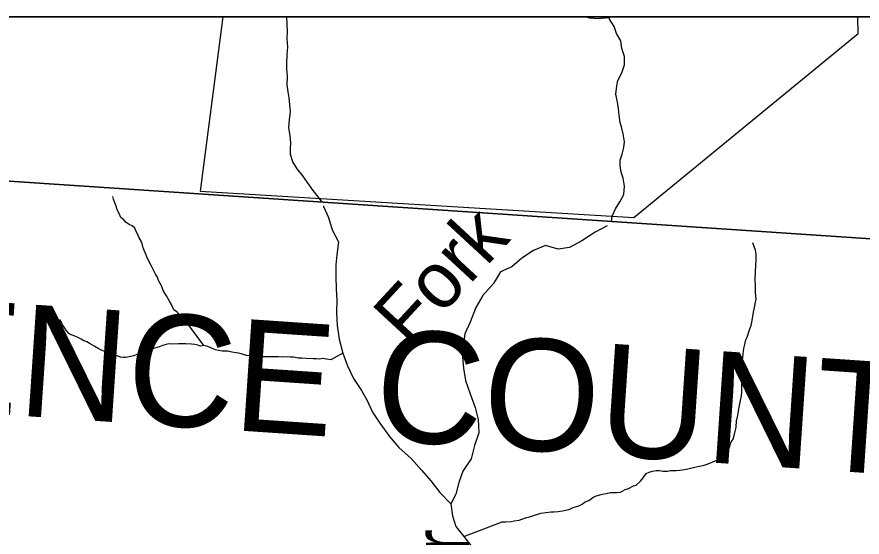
# Model space of a CAD drawing. Extents: x 0 to 34, y 0 to 22.
# Drawn here: x 4.61 to 6.043, y 20.019 to 20.9 of the extents above; entities that cross this region are included whole.
import ezdxf

# ---------------------------------------------------------------- set-up
doc = ezdxf.new("R2010")
doc.units = 0
for name, color, linetype in [('GM_X_County_Text', 7, 'Continuous'), ('GM_X_Minor_River', 7, 'Continuous'), ('GM_X_Minor_River_Text', 7, 'Continuous'), ('GM_X_Township_Road_Text', 7, 'Continuous'), ('GM_X_Unincorporated', 7, 'Continuous'), ('SH_Cut_Line', 7, 'Continuous'), ('SH_Data', 7, 'Continuous')]:
    doc.layers.add(name, color=color, linetype=linetype)

msp = doc.modelspace()

# ---------------------------------------------------------------- linework, layer by layer
at = {"layer": 'GM_X_Minor_River'}
for points in [[(5.1277, 20.5859), (5.1227, 20.5926), (5.1125, 20.6059), (5.1027, 20.6192), (5.0945, 20.6306), (5.085, 20.6424), (5.0775, 20.6542), (5.0737, 20.6671), (5.0738, 20.677), (5.0746, 20.6865), (5.0731, 20.699), (5.0709, 20.7119), (5.0721, 20.7263), (5.0736, 20.7392), (5.0729, 20.751), (5.0714, 20.7631), (5.0696, 20.773), (5.0681, 20.7851), (5.0685, 20.7988), (5.0678, 20.8117), (5.0675, 20.8215), (5.0683, 20.8359), (5.0691, 20.8492), (5.0684, 20.8629), (5.0688, 20.8754), (5.0684, 20.8875), (5.0677, 20.8997), (5.0676, 20.9)], [(5.6145, 20.8986), (5.6071, 20.898), (5.595, 20.8969), (5.581, 20.8981), (5.5725, 20.9)], [(5.6178, 20.5531), (5.6192, 20.5622), (5.625, 20.5751), (5.6318, 20.5865), (5.6387, 20.599), (5.6399, 20.613), (5.638, 20.627), (5.6343, 20.6369), (5.6324, 20.6475), (5.6328, 20.6574), (5.6359, 20.6673), (5.6386, 20.6786), (5.6397, 20.6881), (5.6375, 20.7021), (5.6353, 20.7116), (5.6327, 20.7211), (5.6308, 20.7337), (5.6297, 20.745), (5.6282, 20.7553), (5.6252, 20.769), (5.6272, 20.783), (5.6284, 20.7925), (5.6356, 20.8053), (5.6402, 20.819), (5.6402, 20.833), (5.6357, 20.8467), (5.6335, 20.8592), (5.6267, 20.8717), (5.6222, 20.8839), (5.6143, 20.8961), (5.6146, 20.9)], [(4.9271, 20.3435), (4.8927, 20.3892), (4.8867, 20.3942), (4.8818, 20.3996), (4.8762, 20.4038), (4.8725, 20.4118), (4.8688, 20.4184), (4.8636, 20.4272), (4.861, 20.4321), (4.858, 20.4367), (4.8558, 20.4432), (4.8528, 20.4486), (4.8502, 20.4532), (4.8484, 20.4593), (4.845, 20.4643), (4.8417, 20.4711), (4.838, 20.4777), (4.8342, 20.4849), (4.8302, 20.4937), (4.8283, 20.4983), (4.8261, 20.5033), (4.8243, 20.5086), (4.8228, 20.5136), (4.8206, 20.5201), (4.8173, 20.5258), (4.8147, 20.5323), (4.8117, 20.5377), (4.8099, 20.5419), (4.8054, 20.5461), (4.8005, 20.5484), (4.7952, 20.5519), (4.7914, 20.5562), (4.7862, 20.5604), (4.7832, 20.5669), (4.7799, 20.5734), (4.7781, 20.5791), (4.7758, 20.5849), (4.7736, 20.5914), (4.7729, 20.5955)], [(5.1295, 20.5797), (5.13, 20.579), (5.1382, 20.5603), (5.1445, 20.539), (5.1554, 20.5192), (5.1526, 20.4972), (5.1509, 20.4798), (5.1504, 20.4604), (5.1514, 20.4391), (5.1524, 20.4201), (5.1519, 20.3992), (5.1529, 20.3772), (5.1565, 20.354), (5.1624, 20.3301), (5.1706, 20.3087), (5.1804, 20.2874), (5.1939, 20.2672), (5.2036, 20.2501), (5.2126, 20.2303), (5.2254, 20.212), (5.2415, 20.1891), (5.2573, 20.1704), (5.2784, 20.1521), (5.2965, 20.1315), (5.3115, 20.1139), (5.327, 20.0941), (5.3454, 20.075), (5.3483, 20.0549), (5.3543, 20.0366), (5.3674, 20.0195), (5.3828, 20)], [(5.6108, 20.5458), (5.5904, 20.5352), (5.5676, 20.5205), (5.5467, 20.5096), (5.5273, 20.5063), (5.5061, 20.5125), (5.4856, 20.5042), (5.4661, 20.4914), (5.449, 20.4767), (5.43, 20.4684), (5.4177, 20.4484), (5.4001, 20.4279), (5.3878, 20.4075), (5.3786, 20.3829), (5.3693, 20.3632), (5.3665, 20.3415), (5.3653, 20.3237), (5.367, 20.3047), (5.3703, 20.2841), (5.3781, 20.2613), (5.3867, 20.2381), (5.3919, 20.218), (5.3929, 20.1955), (5.3859, 20.1739), (5.3801, 20.1516), (5.3659, 20.1307), (5.3589, 20.1114), (5.3542, 20.0913), (5.3454, 20.075)], [(5.8547, 20.3773), (5.8563, 20.3857), (5.8587, 20.3997), (5.8599, 20.405), (5.862, 20.4168), (5.8631, 20.4213), (5.8625, 20.4274), (5.8621, 20.4331), (5.8619, 20.4419), (5.8619, 20.4464), (5.8616, 20.4529), (5.8617, 20.4582), (5.8622, 20.4666), (5.8627, 20.481), (5.8631, 20.4855), (5.8632, 20.4924), (5.8629, 20.4981), (5.8622, 20.5046), (5.8574, 20.5175)], [(5.1624, 20.3301), (5.1419, 20.3191), (5.1351, 20.32), (5.1283, 20.3212), (5.1237, 20.3201), (5.1173, 20.3206), (5.1123, 20.321), (5.0998, 20.3212), (5.0926, 20.322), (5.0869, 20.3221), (5.079, 20.3233), (5.0737, 20.3234), (5.0691, 20.3242), (5.06, 20.3236), (5.0536, 20.324), (5.0467, 20.3241), (5.0392, 20.3242), (5.0335, 20.3239), (5.0263, 20.3244), (5.0209, 20.3248), (5.0122, 20.3253), (5.0069, 20.3261), (4.9993, 20.3266), (4.9903, 20.3294), (4.9857, 20.3302), (4.9816, 20.331), (4.9744, 20.3323), (4.9676, 20.3335), (4.9623, 20.3339), (4.9581, 20.334), (4.952, 20.3348), (4.9467, 20.336), (4.9414, 20.3384), (4.9339, 20.3419), (4.9271, 20.3435), (4.921, 20.3424), (4.9165, 20.344), (4.9119, 20.3448), (4.9059, 20.3457), (4.8964, 20.3462), (4.8839, 20.3463), (4.8725, 20.3457), (4.8672, 20.3462), (4.8588, 20.344), (4.8493, 20.3407), (4.8413, 20.3381), (4.8359, 20.3355), (4.8314, 20.3341), (4.8253, 20.3323), (4.8199, 20.3308), (4.8131, 20.3279), (4.8081, 20.3256), (4.7948, 20.3231), (4.7906, 20.3228), (4.7857, 20.3236), (4.7763, 20.3272), (4.7714, 20.3288), (4.7631, 20.3319), (4.7585, 20.3331), (4.7536, 20.3355), (4.748, 20.3382), (4.7423, 20.3417), (4.7344, 20.3463), (4.7287, 20.3498), (4.7234, 20.3514), (4.7189, 20.3541), (4.7144, 20.3561), (4.7068, 20.3596), (4.7019, 20.3616), (4.6978, 20.3635), (4.6929, 20.3697), (4.6899, 20.3743), (4.6873, 20.3785), (4.6855, 20.3827), (4.6829, 20.3873)], [(5.3674, 20.0195), (5.4328, 20.0445), (5.4381, 20.0448), (5.4479, 20.045), (5.4529, 20.0461), (5.4612, 20.0475), (5.4723, 20.0516), (5.4768, 20.0523), (5.4829, 20.0545), (5.4875, 20.0559), (5.4928, 20.0578), (5.4982, 20.0592), (5.5065, 20.0606), (5.5157, 20.0617), (5.5206, 20.0616), (5.5278, 20.0623), (5.535, 20.0633), (5.543, 20.0651), (5.5472, 20.0658), (5.5529, 20.0688), (5.5571, 20.0702), (5.5624, 20.0717), (5.5682, 20.0747), (5.5724, 20.078), (5.5796, 20.081), (5.5861, 20.0858), (5.5907, 20.0881), (5.5979, 20.0903), (5.6025, 20.0913), (5.609, 20.0928), (5.6162, 20.0942), (5.6268, 20.0941), (5.6333, 20.0951), (5.6413, 20.0992), (5.6466, 20.101), (5.655, 20.1055), (5.6596, 20.1069), (5.6672, 20.1137), (5.6719, 20.1193), (5.6769, 20.1265), (5.6818, 20.1287), (5.6875, 20.1305), (5.6936, 20.1316), (5.6989, 20.1315), (5.7058, 20.1307), (5.7126, 20.1306), (5.7175, 20.1313), (5.7274, 20.1315), (5.7339, 20.1322), (5.7415, 20.1333), (5.7472, 20.1343), (5.7593, 20.1372), (5.7643, 20.1383), (5.7753, 20.1404), (5.7818, 20.1426), (5.786, 20.1445), (5.7936, 20.1482), (5.7997, 20.1504), (5.8047, 20.156), (5.8116, 20.1616), (5.8166, 20.1677), (5.8209, 20.1801), (5.824, 20.1847), (5.8268, 20.1953), (5.8292, 20.2047), (5.83, 20.2161), (5.8313, 20.2218), (5.8341, 20.2389), (5.8357, 20.2446), (5.8381, 20.2578), (5.8389, 20.2643), (5.8386, 20.2685), (5.8387, 20.2791), (5.8388, 20.2837), (5.8385, 20.2905), (5.8389, 20.2947), (5.839, 20.303), (5.8394, 20.3072), (5.84, 20.3186), (5.8408, 20.3228), (5.8412, 20.3292), (5.8425, 20.3383), (5.8433, 20.3425), (5.8457, 20.3531), (5.848, 20.3577), (5.8511, 20.3679), (5.8547, 20.3773)]]:
    msp.add_lwpolyline(points, dxfattribs=at)
at = {"layer": 'GM_X_Township_Road_Text'}
msp.add_lwpolyline([(6.0356, 20.9), (4.9589, 20.9), (4.9205, 20.6046), (5.5716, 20.5655), (5.6558, 20.5604), (6.0359, 20.8717)], close=True, dxfattribs=at)
at = {"layer": 'GM_X_Unincorporated'}
msp.add_lwpolyline([(6.769, 20.9), (2.2853, 20.9), (2.418, 20.5866), (2.7473, 19.8121), (2.9553, 19.318), (2.9956, 19.2227), (3.0781, 19.0279), (3.1249, 18.9173), (3.4011, 18.2653), (3.4595, 19.1305), (3.4599, 19.1361), (3.5099, 19.8769), (3.5456, 20.4047), (3.5457, 20.4056), (3.5462, 20.4144), (3.5651, 20.6937), (3.8602, 20.6728), (4.3099, 20.6409), (6.6484, 20.4847), (6.6568, 20.5136)], close=True, dxfattribs=at)
msp.add_lwpolyline([(8.9, 14.2264), (8.9, 20.3234), (8.6245, 20.3436), (7.6038, 20.4229), (7.3955, 20.4364), (6.962, 20.4644), (6.8381, 20.4724), (6.7584, 20.4776), (6.6718, 20.4832), (6.6484, 20.4847), (4.3099, 20.6409), (3.8602, 20.6728), (3.5651, 20.6937), (3.5462, 20.4144), (3.5457, 20.4056), (3.5456, 20.4047), (3.5099, 19.8769)], dxfattribs=at)
at = {"layer": 'SH_Cut_Line'}
for points in [[(4.2937, 16.1161), (4.0882, 16.6114), (3.972, 16.8916), (3.7367, 17.4136), (3.709, 17.484), (3.4011, 18.2653), (3.4595, 19.1305), (3.4599, 19.1361), (3.5099, 19.8769), (3.5456, 20.4047), (3.5457, 20.4056), (3.5462, 20.4144), (3.5651, 20.6937), (3.8602, 20.6728), (4.3099, 20.6409), (6.6484, 20.4847), (6.6568, 20.5136), (6.769, 20.9), (2.1, 20.9), (2.1, 14.1)], [(8.9, 14.1), (8.9, 20.9), (6.769, 20.9), (6.6568, 20.5136), (6.6484, 20.4847), (4.3099, 20.6409), (3.8602, 20.6728), (3.5651, 20.6937), (3.5462, 20.4144), (3.5457, 20.4056), (3.5456, 20.4047), (3.5099, 19.8769), (3.4599, 19.1361), (3.4595, 19.1305), (3.4011, 18.2653), (3.709, 17.484), (3.7367, 17.4136), (3.972, 16.8916), (4.0882, 16.6114), (4.2937, 16.1161)]]:
    msp.add_lwpolyline(points, dxfattribs=at)
at = {"layer": 'SH_Data'}
msp.add_line((2.1, 20.9), (8.9, 20.9), dxfattribs=at)

# ---------------------------------------------------------------- texts
at = {"layer": 'GM_X_County_Text'}
msp.add_text('LAWRENCE COUNTY', height=0.189394, rotation=356.1322, dxfattribs=at).set_placement((3.7106, 20.2855))
at = {"layer": 'GM_X_Minor_River_Text'}
for s, rotation, p in [('Fork', 47.2684, (5.2768, 20.3368)), ('Poplar', 89.9998, (5.3762, 19.6665))]:
    msp.add_text(s, height=0.0947, rotation=rotation, dxfattribs=at).set_placement(p)

doc.saveas('drawing.dxf')
